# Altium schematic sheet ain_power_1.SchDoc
size A4
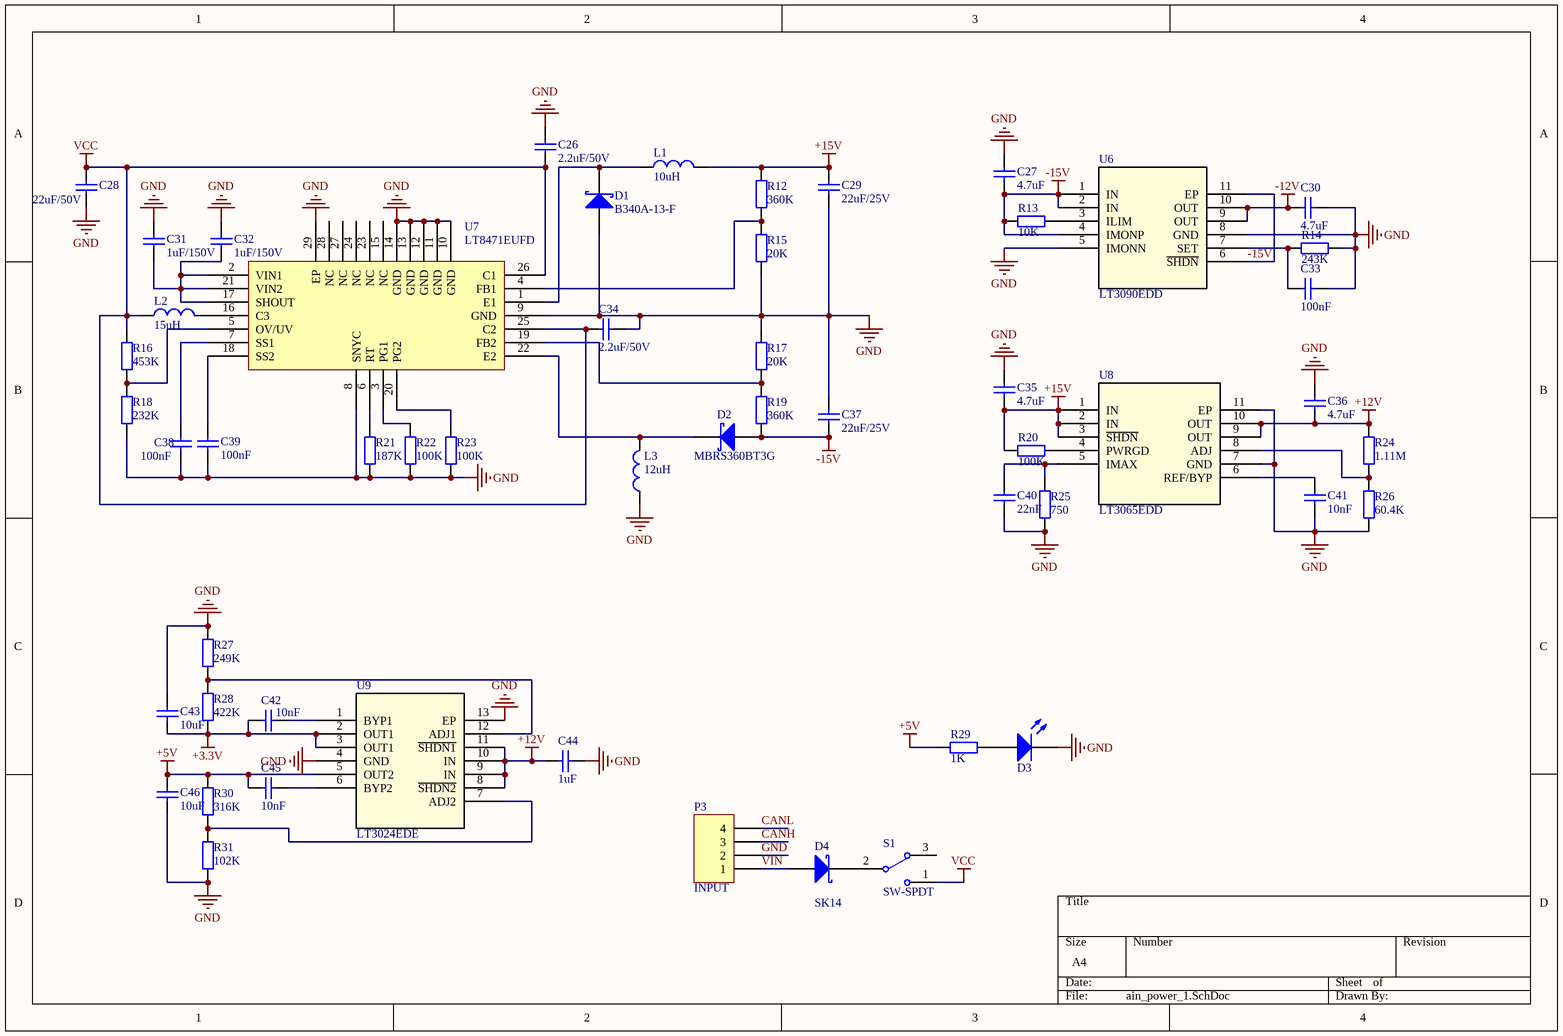
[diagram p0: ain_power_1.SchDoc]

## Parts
C26  value 2.2uF/50V  [C-0603]  (hidden comment: Cap-S)
C27  value 4.7uF  [0402]  (hidden comment: Cap-S)
C28  value 22uF/50V  [C-0603]  (hidden comment: Cap-S)
C29  value 22uF/25V  [C-0805]  (hidden comment: Cap-S)
C30  value 4.7uF  [0402]  (hidden comment: Cap-S)
C31  value 1uF/150V  [C-0603]  (hidden comment: Cap-S)
C32  value 1uF/150V  [C-0603]  (hidden comment: Cap-S)
C33  value 100nF  [0402]  (hidden comment: Cap-S)
C34  value 2.2uF/50V  [C-0603]  (hidden comment: Cap-S)
C35  value 4.7uF  [0402]  (hidden comment: Cap-S)
C36  value 4.7uF  [0402]  (hidden comment: Cap-S)
C37  value 22uF/25V  [C-0805]  (hidden comment: Cap-S)
C38  value 100nF  [0402]  (hidden comment: Cap-S)
C39  value 100nF  [0402]  (hidden comment: Cap-S)
C40  value 22nF  [0402]  (hidden comment: Cap-S)
C41  value 10nF  [0402]  (hidden comment: Cap-S)
C42  value 10nF  [0402]  (hidden comment: Cap-S)
C43  value 10uF  [0402]  (hidden comment: Cap-S)
C44  value 1uF  [0402]  (hidden comment: Cap-S)
C45  value 10nF  [0402]  (hidden comment: Cap-S)
C46  value 10uF  [0402]  (hidden comment: Cap-S)
D1  B340A-13-F  [SMA(DO-214AC)]
D2  MBRS360BT3G  [SMB(DO-214AA)]
D3  LED0  [0402]  (value not drawn)
D4  SK14  [SMA(DO-214AC)]
L1  value 10uH  [L-SMD-4]  (hidden comment: SLW4030S100MST)
L2  value 15uH  [L-SMD-3]  (hidden comment: SWPA3015S150MT)
L3  value 12uH  [L-SMD-5]  (hidden comment: FNR5040S120MT)
P3  INPUT  [LZ1R-3.5-4P]
R12  value 360K  [0402]  (hidden comment: Res1)
R13  value 10K  [0402]  (hidden comment: Res1)
R14  value 243K  [0402]  (hidden comment: Res1)
R15  value 20K  [0402]  (hidden comment: Res1)
R16  value 453K  [0402]  (hidden comment: Res1)
R17  value 20K  [0402]  (hidden comment: Res1)
R18  value 232K  [0402]  (hidden comment: Res1)
R19  value 360K  [0402]  (hidden comment: Res1)
R20  value 100K  [0402]  (hidden comment: Res1)
R21  value 187K  [0402]  (hidden comment: Res1)
R22  value 100K  [0402]  (hidden comment: Res1)
R23  value 100K  [0402]  (hidden comment: Res1)
R24  value 1.11M  [0402]  (hidden comment: Res1)
R25  value 750  [0402]  (hidden comment: Res1)
R26  value 60.4K  [0402]  (hidden comment: Res1)
R27  value 249K  [0402]  (hidden comment: Res1)
R28  value 422K  [0402]  (hidden comment: Res1)
R29  value 1K  [0402]  (hidden comment: Res1)
R30  value 316K  [0402]  (hidden comment: Res1)
R31  value 102K  [0402]  (hidden comment: Res1)
S1  SW-SPDT  [SK-12D07(1P2T)]
U6  LT3090EDD  [DFN-10_DD]
U7  LT8471EUFD  [LT8471]
U8  LT3065EDD  [DFN-10_DD]
U9  LT3024EDE  [DFN-12_DE]

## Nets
+3.3V: C42.2 C43.1 R28.1 U9.2(OUT1) U9.3(OUT1)
+5V: C45.2 C46.2 R29.1 R30.2 U9.5(OUT2)
+12V: C36.1 C44.2 R24.2 U8.9(OUT) U8.10(OUT) U9.8(~{SHDN2}) U9.9(IN) U9.10(IN) U9.11(~{SHDN1})
+15V: C29.2 C35.1 L1.2 R12.2 R20.2 U8.1(IN) U8.2(IN) U8.3(~{SHDN})
-12V: C30.1 U6.9(OUT) U6.10(OUT)
-15V: C27.2 C37.1 D2.1(A) R13.2 R19.1 U6.1(IN) U6.2(IN) U6.4(IMONP) U6.6(~{SHDN}) U6.11(EP)
GND: C26.2 C27.1 C28.1 C29.1 C30.2 C31.2 C32.2 C33.2 C34.2 C35.2 C36.2 C37.2 C38.1 C39.1 C40.1 C41.1 C43.2 C44.1 C46.1 D1.1(A) D3.2(K) L3.1 P3.2 R14.2 R15.1 R17.2 R18.1 R21.1 R22.1 R23.1 R25.1 R26.1 R27.2 R31.1 U6.5(IMONN) U6.8(GND) U7.8(SNYC) U7.9(GND) U7.10(GND) U7.11(GND) U7.12(GND) U7.13(GND) U7.14(GND) U7.29(EP) U8.7(GND) U8.11(EP) U9.4(GND) U9.13(EP)
VCC: C26.1 C28.2 C34.1 L2.1 R16.2 S1.1 U7.25(C2) U7.26(C1)
CANH: P3.3
CANL: P3.4
VIN: D4.1(A) P3.1
NetC31_1: C31.1 C32.1 U7.2(VIN1) U7.17(SHOUT) U7.21(VIN2)
NetC33_1: C33.1 R14.1 U6.7(SET)
NetC38_2: C38.2 U7.7(SS1)
NetC39_2: C39.2 U7.18(SS2)
NetC40_2: C40.2 R25.2 U8.5(IMAX)
NetC41_2: C41.2 U8.6(REF/BYP)
NetC42_1: C42.1 U9.1(BYP1)
NetC45_1: C45.1 U9.6(BYP2)
NetD1_2: D1.2(K) L1.1 U7.1(E1)
NetD2_2: D2.2(K) L3.2 U7.22(E2)
NetD3_1: D3.1(A) R29.2
NetD4_2: D4.2(K) S1.2
NetL2_2: L2.2 U7.16(C3)
NetR12_1: R12.1 R15.2 U7.4(FB1)
NetR13_1: R13.1 U6.3(ILIM)
NetR16_1: R16.1 R18.2 U7.5(OV/UV)
NetR17_1: R17.1 R19.2 U7.19(FB2)
NetR20_1: R20.1 U8.4(PWRGD)
NetR21_2: R21.2 U7.6(RT)
NetR22_2: R22.2 U7.3(PG1)
NetR23_2: R23.2 U7.20(PG2)
NetR24_1: R24.1 R26.2 U8.8(ADJ)
NetR27_1: R27.1 R28.2 U9.12(ADJ1)
NetR30_1: R30.1 R31.2 U9.7(ADJ2)

Not connected (* = marked no-connect by the designer): S1 3; U7 15(NC) 23(NC) 24(NC) 27(NC) 28(NC)

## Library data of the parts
C26-C46 = Cap-S: 贴片瓷片电容
D1 = Diode-Schottky: 肖特基二极管; Type: SS14; Value: 100V/3A
D2 = Diode-Schottky: 肖特基二极管; Type: SS14; Value: 60V/3A
D3 = LED0: 发光二极管
D4 = Diode-Schottky: 肖特基二极管; Type: SS14
L1-L3 = Inductor: 电感; Code_IEC: 1005
P3 = Header 4: Header, 4-Pin
R12-R31 = Res1: 贴片电阻
S1 = SW-SPDT: 开关
U6 = LT3090: LDO positive; Manufacturer_Part_Number: lt3090edd#pbf; Vendor: Linear Technology
U7 = LT8471: DC-DC dual channel
U8 = LT3065: LDO negative; Manufacturer_Part_Number: lt3065edd#trpbf; Vendor: Linear Technology
U9 = LT3024: LDO dual output; Vendor: Linear Technology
